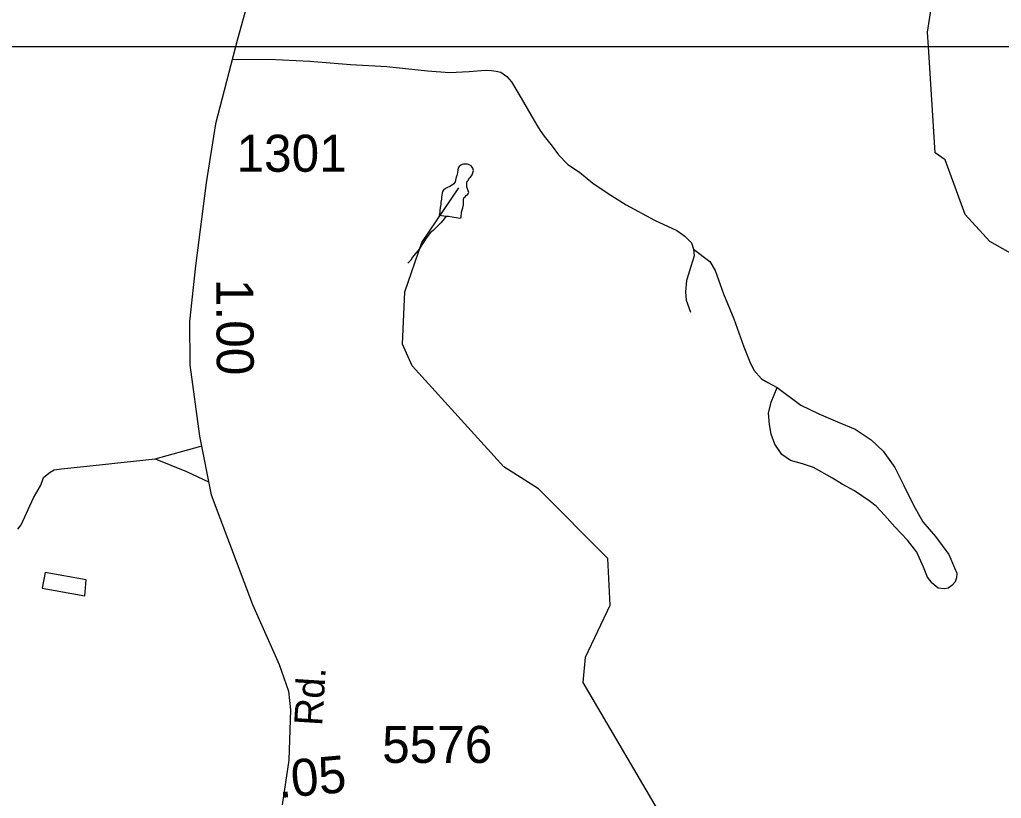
# Model space of a CAD drawing. Extents: x 2001466 to 2224147, y 644118 to 847247.
# Drawn here: x 2065678 to 2068990, y 655639 to 658266 of the extents above; entities that cross this region are included whole.
import ezdxf

# ---------------------------------------------------------------- set-up
doc = ezdxf.new("R2010")
doc.units = 0
for name, color, linetype in [('Exist Hydrographic Creek Single Shore', 7, 'Continuous'), ('Exist Hydrographic Misc Water Feature', 7, 'Continuous'), ('Exist Road Non-System Type 51', 7, 'Continuous'), ('Exist Road Secondary Mileage Hundredths English Label', 7, 'Continuous'), ('Exist Road Secondary Type 51 Attributed', 7, 'Continuous'), ('Exist Road Secondary Type 51 Label', 7, 'Continuous'), ('Exist Road Secondary Type 51 Number Label', 7, 'Continuous'), ('Map Preparation Inset Cut Line', 7, 'Continuous')]:
    doc.layers.add(name, color=color, linetype=linetype)

msp = doc.modelspace()

# ---------------------------------------------------------------- linework, layer by layer
at = {"layer": 'Exist Hydrographic Creek Single Shore'}
for points in [[(2068744.1, 658173.9), (2068740.9, 658223.9), (2068766, 658384.2), (2068714.9, 658798.6), (2068540, 659225.3), (2068298, 659414), (2068188.9, 659704.9), (2068137.9, 659988.1), (2068038, 660098.4), (2067813.1, 660198.1), (2067662, 660614.6), (2067619.9, 660973), (2067670, 661139.3), (2067762.3, 661294)], [(2069234.9, 657357.6), (2068950.9, 657517.5), (2068867.9, 657607.8), (2068800.8, 657792.9), (2068767, 657816.5), (2068744.1, 658173.9)], [(2069158.8, 653143.3), (2068774.8, 653433.2), (2068566.9, 653493.3), (2068524.8, 653533.5), (2068449.8, 653741.7), (2068390.7, 654031.6), (2068164.7, 654482.4), (2068047.9, 654839.1), (2067988.8, 655165.1), (2067963.8, 655182), (2067871.9, 655531.6), (2067578.9, 656029.7), (2067586.9, 656114.8), (2067670, 656290.3), (2067662, 656447.9), (2067428, 656682.3), (2067310.9, 656756.9), (2067001.9, 657097.8), (2066968.9, 657170.7), (2066976.9, 657347.7), (2067034.9, 657513.8), (2067160, 657698.3)]]:
    msp.add_lwpolyline(points, dxfattribs=at)
at = {"layer": 'Exist Hydrographic Misc Water Feature'}
for points in [[(2067116.9, 657602.3), (2067124.9, 657602.3), (2067136.8, 657600.3), (2067151, 657598.4), (2067162.9, 657596.4), (2067167, 657598.4), (2067169, 657616.4), (2067172.9, 657630.4), (2067175, 657640.4), (2067175, 657648.4), (2067175, 657654.4), (2067174.8, 657658.4), (2067176.8, 657664.4), (2067180.7, 657668.4), (2067184.8, 657672.4), (2067188.7, 657674.5), (2067190.7, 657678.5), (2067192.8, 657682.5), (2067190.7, 657688.5), (2067188.7, 657694.5), (2067186.9, 657700.4), (2067186.9, 657706.4), (2067186.9, 657712.5), (2067186.9, 657718.4), (2067190.7, 657722.5), (2067194.6, 657730.5), (2067198.7, 657734.5), (2067204.7, 657742.5), (2067206.7, 657748.5), (2067208.6, 657756.5), (2067206.7, 657764.5), (2067204.7, 657768.5), (2067200.6, 657772.5), (2067196.7, 657774.4), (2067192.6, 657776.4), (2067188.7, 657778.4), (2067182.8, 657778.4), (2067174.8, 657778.4), (2067170.7, 657776.4), (2067166.8, 657774.4), (2067160.6, 657770.4), (2067158.8, 657766.4), (2067156.7, 657760.4), (2067154.7, 657748.4), (2067152.6, 657740.3), (2067150.8, 657734.3), (2067148.7, 657724.3), (2067146.9, 657718.3), (2067142.8, 657712.3), (2067134.8, 657706.4), (2067128.8, 657702.4), (2067118.8, 657698.3), (2067108.7, 657692.3), (2067104.8, 657686.3), (2067102.8, 657680.3), (2067100.7, 657666.3), (2067100.9, 657660.3), (2067098.9, 657650.3), (2067098.9, 657642.3), (2067096.8, 657632.3), (2067095, 657622.3), (2067095, 657616.3), (2067092.9, 657606.3), (2067108.9, 657604.3), (2067116.9, 657602.3)], [(2067116.9, 657602.3), (2067105, 657588.3), (2067099.1, 657580.3), (2067093.1, 657574.3), (2067089, 657570.3), (2067079, 657560.3), (2067073, 657554.3), (2067063, 657546.3), (2067057.1, 657538.3), (2067049.3, 657528.2), (2067041.3, 657516.2), (2067035.1, 657506.2), (2067029.2, 657496.2), (2067021.2, 657486.2), (2067013.2, 657476.2), (2067003.3, 657464.2), (2066997.4, 657454.2), (2066993.3, 657450.2), (2066987.3, 657444.1)], [(2065763.6, 656400.1), (2065753.5, 656348), (2065897.5, 656322.4), (2065901.6, 656376.3), (2065763.6, 656400.1)]]:
    msp.add_lwpolyline(points, dxfattribs=at)
at = {"layer": 'Exist Road Non-System Type 51'}
msp.add_line((2066135.3, 656783.7), (2066289.5, 656826.8), dxfattribs=at)
for points in [[(2066394.4, 658131.1), (2066518.7, 658131.9), (2066656.6, 658125.1), (2066794.4, 658114.3), (2066916.2, 658107.8), (2067053.9, 658093), (2067127.8, 658087.5), (2067193.9, 658090.2), (2067250, 658095), (2067270, 658094.6), (2067285.9, 658092.3), (2067301.8, 658088), (2067321.5, 658073.6), (2067337.2, 658055.3), (2067370, 658000.6), (2067422.2, 657909.5), (2067433.8, 657891.3), (2067447.4, 657873), (2067474.7, 657838.5), (2067496.2, 657810), (2067527.5, 657777.4), (2067567, 657750.6), (2067612.2, 657713.7), (2067663.5, 657678.6), (2067724.7, 657641.4), (2067819.7, 657589.5), (2067894.9, 657553.9), (2067922.6, 657535.4), (2067944.1, 657512.9), (2067951.7, 657490.8)], [(2067951.7, 657490.8), (2067953.2, 657468.8), (2067942.5, 657433), (2067934, 657407.2), (2067927.5, 657385.3), (2067924.7, 657347.3), (2067926.2, 657319.3), (2067941.4, 657279)], [(2067951.7, 657490.8), (2068006.8, 657449.7), (2068024.2, 657419.3), (2068052.6, 657340.7), (2068086.9, 657256), (2068121, 657161.4), (2068141.9, 657110.9), (2068155.4, 657082.7), (2068180.8, 657054.1), (2068202.5, 657041.7), (2068234.2, 657025.1)], [(2068234.2, 657025.1), (2068313, 656965.5), (2068374.4, 656936.2), (2068437.8, 656908.9), (2068497.3, 656883.7), (2068550.6, 656848.6), (2068591.8, 656809.8), (2068630.7, 656755), (2068661.4, 656694.4), (2068694.1, 656627.7), (2068724.9, 656571.1), (2068767.9, 656522.2), (2068812.7, 656461.3), (2068831.8, 656416.9), (2068839.4, 656398.8), (2068839.1, 656382.8), (2068834.8, 656368.9), (2068822.6, 656357.1), (2068810.4, 656347.4), (2068798.4, 656345.6), (2068776.4, 656348), (2068756.7, 656364.4), (2068741.1, 656384.8), (2068727.8, 656419), (2068704.9, 656469.5), (2068673.7, 656510.1), (2068630.6, 656555), (2068595.4, 656593.7), (2068568, 656624.3), (2068544.4, 656642.8), (2068495.1, 656675.8), (2068453.5, 656698.6), (2068420, 656719.3), (2068356.7, 656754.6), (2068318.9, 656767.3), (2068279.2, 656778.1), (2068249.6, 656798.7), (2068226.3, 656833.2), (2068213, 656867.5), (2068207.6, 656899.6), (2068204.4, 656937.7), (2068213.2, 656975.5), (2068234.2, 657025.1)], [(2065671.6, 656546.4), (2065682.7, 656560.9), (2065724.6, 656652), (2065747.4, 656693.5), (2065753.7, 656707.4), (2065758, 656721.3), (2065770.2, 656731.1), (2065780.4, 656738.9), (2065794.5, 656746.6), (2065818.6, 656750.1), (2065956.9, 656765.3), (2066135.3, 656783.7)], [(2066135.3, 656783.7), (2066240.4, 656741.5), (2066315.3, 656706.7)]]:
    msp.add_lwpolyline(points, dxfattribs=at)
at = {"layer": 'Exist Road Secondary Type 51 Attributed'}
msp.add_lwpolyline([(2067040.6, 660721.7), (2066976.9, 660324.6), (2066927.3, 660052.1), (2066840.7, 659699.3), (2066737.3, 659350.7), (2066525.1, 658605), (2066413.2, 658199.3), (2066338.8, 657914.1), (2066307.1, 657715.6), (2066271.2, 657434.6), (2066250.6, 657247.6), (2066251.7, 657100.8), (2066285, 656860), (2066324, 656662.4), (2066462.8, 656292.7), (2066553.6, 656089.9), (2066584.7, 656000.2), (2066591.1, 655937.8), (2066585.8, 655767.8), (2066563.6, 655617)], dxfattribs=at)
at = {"layer": 'Map Preparation Inset Cut Line'}
for p, q in [((2066379.7, 658173.9), (2063404.3, 658173.9)), ((2068744.1, 658173.9), (2066379.7, 658173.9)), ((2070058.4, 658173.9), (2068744.1, 658173.9))]:
    msp.add_line(p, q, dxfattribs=at)

# ---------------------------------------------------------------- texts
at = {"layer": 'Exist Road Secondary Mileage Hundredths English Label'}
for s, rotation, p in [('1.00', 270.4119, (2066340.6, 657390.6)), ('.05', 5.1386, (2066552.4, 655639.4))]:
    msp.add_text(s, height=125, rotation=rotation, dxfattribs=at).set_placement(p)
at = {"layer": 'Exist Road Secondary Type 51 Label'}
msp.add_text('Rd.', height=95, rotation=86.3868, dxfattribs=at).set_placement((2066698.3, 655881.5))
at = {"layer": 'Exist Road Secondary Type 51 Number Label'}
for s, p in [('1301', (2066409.2, 657752.4)), ('5576', (2066900.8, 655758.3))]:
    msp.add_text(s, height=125, dxfattribs=at).set_placement(p)

doc.saveas('drawing.dxf')
